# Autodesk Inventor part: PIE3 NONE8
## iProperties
Shininess: 64.0
Length Units: 11269
Angle Units: 11279
Time Units: 11290
Mass Units: 11286
Length Display Precision: 3
Angle Display Precision: 2
Compacted: True
Part Number: PIE3 NONE8
Document SubType Name: Modeling
Created: 2004-08
Designer: John Blackburn
Manufacturer: Standard
Standards Organization: Custom
Density: 0.0
Volumn: 0.0
Area: 0.0
PropertySet Name: Model Information
Control State: 0
Master: False
Checked Out: False
Author: John Blackburn
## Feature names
1. Erst1
